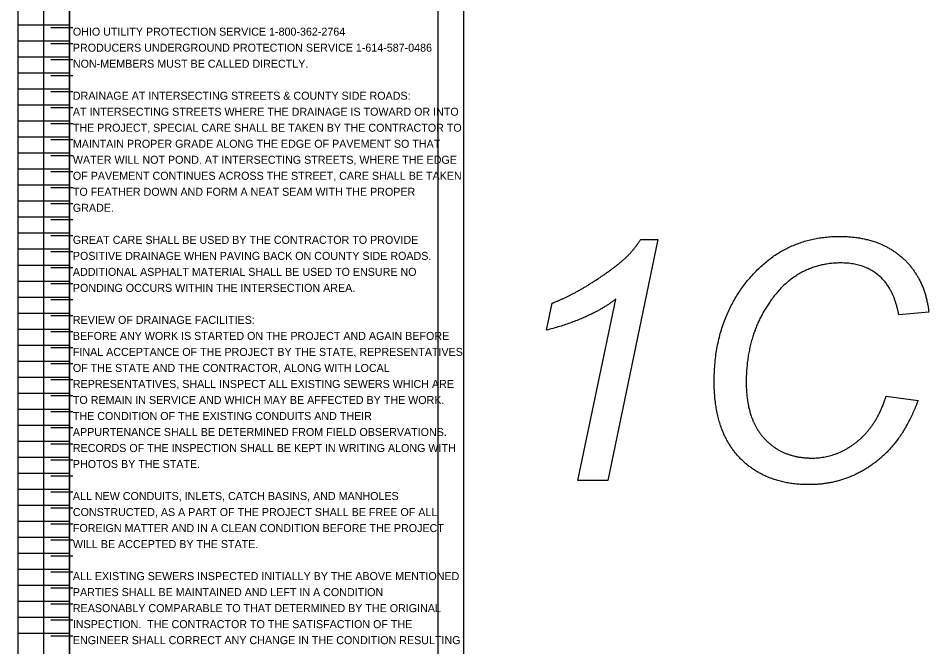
# Model space of a CAD drawing. Extents: x 12316 to 12541, y 1124 to 1850.
# Drawn here: x 12521.92 to 12537.85, y 1794.68 to 1805.67 of the extents above; entities that cross this region are included whole.
import ezdxf

# ---------------------------------------------------------------- set-up
doc = ezdxf.new("R2010")
doc.units = 0
doc.layers.add('SC_Scratch1', color=7, linetype='Continuous')
doc.layers.add('SH_Data', color=7, linetype='Continuous')

msp = doc.modelspace()

# ---------------------------------------------------------------- linework, layer by layer
at = {"layer": 'SC_Scratch1'}
for p, q in [((12521.919, 1789.311), (12521.919, 1809.471)), ((12522.819, 1789.311), (12522.819, 1809.471)), ((12522.819, 1789.311), (12522.819, 1809.471)), ((12522.819, 1809.471), (12522.819, 1789.311)), ((12529.259, 1809.471), (12529.259, 1789.311)), ((12521.919, 1805.551), (12522.819, 1805.551)), ((12522.876, 1805.501), (12522.492, 1805.501)), ((12521.919, 1805.271), (12522.819, 1805.271)), ((12522.876, 1805.221), (12522.492, 1805.221)), ((12521.919, 1804.991), (12522.819, 1804.991)), ((12522.876, 1804.941), (12522.492, 1804.941)), ((12521.919, 1804.711), (12522.819, 1804.711)), ((12522.876, 1804.661), (12522.492, 1804.661)), ((12521.919, 1804.431), (12522.819, 1804.431)), ((12522.876, 1804.381), (12522.492, 1804.381)), ((12521.919, 1804.151), (12522.819, 1804.151)), ((12522.876, 1804.101), (12522.492, 1804.101)), ((12521.919, 1803.871), (12522.819, 1803.871)), ((12522.876, 1803.821), (12522.492, 1803.821)), ((12521.919, 1803.591), (12522.819, 1803.591)), ((12522.876, 1803.541), (12522.492, 1803.541)), ((12521.919, 1803.311), (12522.819, 1803.311)), ((12522.876, 1803.261), (12522.492, 1803.261)), ((12521.919, 1803.031), (12522.819, 1803.031)), ((12522.876, 1802.981), (12522.492, 1802.981)), ((12521.919, 1802.751), (12522.819, 1802.751)), ((12522.876, 1802.701), (12522.492, 1802.701)), ((12521.919, 1802.471), (12522.819, 1802.471)), ((12522.876, 1802.421), (12522.492, 1802.421)), ((12521.919, 1802.191), (12522.819, 1802.191)), ((12522.876, 1802.141), (12522.492, 1802.141)), ((12521.919, 1801.911), (12522.819, 1801.911)), ((12522.876, 1801.861), (12522.492, 1801.861)), ((12521.919, 1801.631), (12522.819, 1801.631)), ((12522.876, 1801.581), (12522.492, 1801.581)), ((12521.919, 1801.351), (12522.819, 1801.351)), ((12522.876, 1801.301), (12522.492, 1801.301)), ((12521.919, 1801.071), (12522.819, 1801.071)), ((12522.876, 1801.021), (12522.492, 1801.021)), ((12521.919, 1800.791), (12522.819, 1800.791)), ((12522.876, 1800.741), (12522.492, 1800.741)), ((12531.166, 1800.212), (12531.263, 1800.683)), ((12521.919, 1800.511), (12522.819, 1800.511)), ((12522.876, 1800.461), (12522.492, 1800.461)), ((12537.852, 1800.529), (12537.327, 1800.481)), ((12521.919, 1800.231), (12522.819, 1800.231)), ((12522.876, 1800.181), (12522.492, 1800.181)), ((12521.919, 1799.951), (12522.819, 1799.951)), ((12522.876, 1799.901), (12522.492, 1799.901)), ((12521.919, 1799.671), (12522.819, 1799.671)), ((12522.876, 1799.621), (12522.492, 1799.621)), ((12521.919, 1799.391), (12522.819, 1799.391)), ((12522.876, 1799.341), (12522.492, 1799.341)), ((12521.919, 1799.111), (12522.819, 1799.111)), ((12522.876, 1799.061), (12522.492, 1799.061)), ((12537.107, 1799.06), (12537.664, 1798.983)), ((12521.919, 1798.831), (12522.819, 1798.831)), ((12522.876, 1798.781), (12522.492, 1798.781)), ((12521.919, 1798.551), (12522.819, 1798.551)), ((12522.876, 1798.501), (12522.492, 1798.501)), ((12521.919, 1798.271), (12522.819, 1798.271)), ((12522.876, 1798.221), (12522.492, 1798.221)), ((12521.919, 1797.991), (12522.819, 1797.991)), ((12522.876, 1797.941), (12522.492, 1797.941)), ((12521.919, 1797.711), (12522.819, 1797.711)), ((12522.876, 1797.661), (12522.492, 1797.661)), ((12521.919, 1797.431), (12522.819, 1797.431)), ((12522.876, 1797.381), (12522.492, 1797.381)), ((12521.919, 1797.151), (12522.819, 1797.151)), ((12522.876, 1797.101), (12522.492, 1797.101)), ((12521.919, 1796.871), (12522.819, 1796.871)), ((12522.876, 1796.821), (12522.492, 1796.821)), ((12521.919, 1796.591), (12522.819, 1796.591)), ((12522.876, 1796.541), (12522.492, 1796.541)), ((12521.919, 1796.311), (12522.819, 1796.311)), ((12522.876, 1796.261), (12522.492, 1796.261)), ((12521.919, 1796.031), (12522.819, 1796.031)), ((12522.876, 1795.981), (12522.492, 1795.981)), ((12521.919, 1795.751), (12522.819, 1795.751)), ((12522.876, 1795.701), (12522.492, 1795.701)), ((12521.919, 1795.471), (12522.819, 1795.471)), ((12522.876, 1795.421), (12522.492, 1795.421)), ((12521.919, 1795.191), (12522.819, 1795.191)), ((12522.876, 1795.141), (12522.492, 1795.141)), ((12521.919, 1794.911), (12522.819, 1794.911)), ((12522.876, 1794.861), (12522.492, 1794.861))]:
    msp.add_line(p, q, dxfattribs=at)
msp.add_lwpolyline([(12522.369, 1809.471), (12529.709, 1809.471), (12529.709, 1789.311), (12522.369, 1789.311)], close=True, dxfattribs=at)
msp.add_lwpolyline([(12532.811, 1801.797), (12533.111, 1801.797), (12532.234, 1797.581), (12531.712, 1797.581), (12532.375, 1800.754)], dxfattribs=at)
for points in [[(12532.593, 1801.52), (12532.707, 1801.634), (12532.811, 1801.797)], [(12534.78, 1801.19), (12535.387, 1801.851), (12536.29, 1801.851)], [(12536.29, 1801.851), (12536.958, 1801.851), (12537.372, 1801.493)], [(12532.027, 1801.086), (12532.404, 1801.334), (12532.593, 1801.52)], [(12536.316, 1801.387), (12535.545, 1801.387), (12535.069, 1800.703)], [(12536.984, 1801.162), (12536.725, 1801.387), (12536.316, 1801.387)], [(12537.372, 1801.493), (12537.786, 1801.134), (12537.852, 1800.529)], [(12531.263, 1800.683), (12531.65, 1800.837), (12532.027, 1801.086)], [(12534.097, 1799.314), (12534.097, 1800.448), (12534.78, 1801.19)], [(12537.327, 1800.481), (12537.244, 1800.937), (12536.984, 1801.162)], [(12532.375, 1800.754), (12531.945, 1800.416), (12531.166, 1800.212)], [(12535.069, 1800.703), (12534.658, 1800.113), (12534.658, 1799.303)], [(12534.546, 1797.977), (12534.097, 1798.444), (12534.097, 1799.314)], [(12534.658, 1799.303), (12534.658, 1798.656), (12534.976, 1798.315)], [(12536.593, 1798.258), (12536.946, 1798.542), (12537.107, 1799.06)], [(12537.664, 1798.983), (12537.4, 1798.255), (12536.895, 1797.883)], [(12534.976, 1798.315), (12535.294, 1797.975), (12535.805, 1797.975)], [(12535.805, 1797.975), (12536.24, 1797.975), (12536.593, 1798.258)], [(12535.761, 1797.51), (12534.995, 1797.51), (12534.546, 1797.977)], [(12536.895, 1797.883), (12536.39, 1797.51), (12535.761, 1797.51)]]:
    msp.add_open_spline(points, degree=2, dxfattribs=at)

# ---------------------------------------------------------------- texts
at = {"layer": 'SH_Data'}
for s, p in [('OHIO UTILITY PROTECTION SERVICE 1-800-362-2764', (12522.876, 1805.361)), ('PRODUCERS UNDERGROUND PROTECTION SERVICE 1-614-587-0486', (12522.876, 1805.081)), ('NON-MEMBERS MUST BE CALLED DIRECTLY.', (12522.876, 1804.801)), ('DRAINAGE AT INTERSECTING STREETS & COUNTY SIDE ROADS:', (12522.876, 1804.241)), ('AT INTERSECTING STREETS WHERE THE DRAINAGE IS TOWARD OR INTO ', (12522.876, 1803.961)), ('THE PROJECT, SPECIAL CARE SHALL BE TAKEN BY THE CONTRACTOR TO ', (12522.876, 1803.681)), ('MAINTAIN PROPER GRADE ALONG THE EDGE OF PAVEMENT SO THAT ', (12522.876, 1803.401)), ('WATER WILL NOT POND. AT INTERSECTING STREETS, WHERE THE EDGE ', (12522.876, 1803.121)), ('OF PAVEMENT CONTINUES ACROSS THE STREET, CARE SHALL BE TAKEN ', (12522.876, 1802.841)), ('TO FEATHER DOWN AND FORM A NEAT SEAM WITH THE PROPER ', (12522.876, 1802.561)), ('GRADE.', (12522.876, 1802.281)), ('GREAT CARE SHALL BE USED BY THE CONTRACTOR TO PROVIDE ', (12522.876, 1801.721)), ('POSITIVE DRAINAGE WHEN PAVING BACK ON COUNTY SIDE ROADS. ', (12522.876, 1801.441)), ('ADDITIONAL ASPHALT MATERIAL SHALL BE USED TO ENSURE NO ', (12522.876, 1801.161)), ('PONDING OCCURS WITHIN THE INTERSECTION AREA.', (12522.876, 1800.881)), ('REVIEW OF DRAINAGE FACILITIES:', (12522.876, 1800.321)), ('BEFORE ANY WORK IS STARTED ON THE PROJECT AND AGAIN BEFORE ', (12522.876, 1800.041)), ('FINAL ACCEPTANCE OF THE PROJECT BY THE STATE, REPRESENTATIVES ', (12522.876, 1799.761)), ('OF THE STATE AND THE CONTRACTOR, ALONG WITH LOCAL ', (12522.876, 1799.481)), ('REPRESENTATIVES, SHALL INSPECT ALL EXISTING SEWERS WHICH ARE ', (12522.876, 1799.201)), ('TO REMAIN IN SERVICE AND WHICH MAY BE AFFECTED BY THE WORK.  ', (12522.876, 1798.921)), ('THE CONDITION OF THE EXISTING CONDUITS AND THEIR ', (12522.876, 1798.641)), ('APPURTENANCE SHALL BE DETERMINED FROM FIELD OBSERVATIONS.  ', (12522.876, 1798.361)), ('RECORDS OF THE INSPECTION SHALL BE KEPT IN WRITING ALONG WITH ', (12522.876, 1798.081)), ('PHOTOS BY THE STATE.', (12522.876, 1797.801)), ('ALL NEW CONDUITS, INLETS, CATCH BASINS, AND MANHOLES ', (12522.876, 1797.241)), ('CONSTRUCTED, AS A PART OF THE PROJECT SHALL BE FREE OF ALL ', (12522.876, 1796.961)), ('FOREIGN MATTER AND IN A CLEAN CONDITION BEFORE THE PROJECT ', (12522.876, 1796.681)), ('WILL BE ACCEPTED BY THE STATE.', (12522.876, 1796.401)), ('ALL EXISTING SEWERS INSPECTED INITIALLY BY THE ABOVE MENTIONED ', (12522.876, 1795.841)), ('PARTIES SHALL BE MAINTAINED AND LEFT IN A CONDITION ', (12522.876, 1795.561)), ('REASONABLY COMPARABLE TO THAT DETERMINED BY THE ORIGINAL ', (12522.876, 1795.281)), ('INSPECTION.  THE CONTRACTOR TO THE SATISFACTION OF THE ', (12522.876, 1795.001)), ('ENGINEER SHALL CORRECT ANY CHANGE IN THE CONDITION RESULTING ', (12522.876, 1794.721))]:
    msp.add_text(s, height=0.14, dxfattribs=at).set_placement(p)

doc.saveas('drawing.dxf')
